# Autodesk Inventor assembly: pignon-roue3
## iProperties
Author: Administrateur
Created: 2001-04
Part Number: pignon-roue3
Document SubType Name: Assemblage
Designer: Administrateur
Control State: 0
Master: False
Checked Out: False
PropertySet Name: Design Tracking Control
Shininess: 60.0
PropertySet Name: _Private Model Information
Density: 0.0
Volumn: 0.0
Area: 0.0
PropertySet Name: Model Information
